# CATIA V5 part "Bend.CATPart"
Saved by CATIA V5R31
Part number: Bend
Bounding box of the stored display mesh (mm): x -50 to 50, y -150 to 15, z -50 to 115
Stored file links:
  D:\PROJECTS\Project 2021\US EDITION\CATIA V5 6R 2021\Resources\Part Files\c12_catia_v5_6r2021_prt\c12_catia_v5-6r2021 figr_12-39\Bend.CATPart
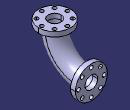
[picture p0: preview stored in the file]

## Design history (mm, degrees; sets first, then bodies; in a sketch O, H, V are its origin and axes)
Body1 (main body)
  Sketch1 on yz-plane, origin (0, 0, 0), H (0, 1, 0), V (0, 0, 1)
    arc A1 centre (0, 100) radius 100 from (-100, 100) to (0, 0) ccw
    point P1 (0, 100)
    coincidence: P1 V
  Sketch2 on zx-plane, origin (0, 0, 0), H (-1, 0, 0), V (0, 0, 1)
    circle A1 centre (0, 0) radius 30
    point P1 (0, -30)
    radius A1 = 30
    coincidence: A1 P1, P1 V
  Rib1: profile Sketch2, centre curve Sketch1
  Sketch3 on face of Rib1, origin (0, 0, 0), H (-1, 0, 0), V (0, 0, 1)
    circle A1 centre (0, 0) radius 50
    point P1 (0, -50)
    radius A1 = 50
    coincidence: A1 P1, P1 V
  Pad1: profile Sketch3, direction (0, 1, 0), length 15
  Sketch4 on face of Rib1, origin (0, 0, 100), H (1, 0, 0), V (0, 1, 0)
    circle A1 centre (0, -100) radius 50
    point P1 (0, -100)
    reference projected circle E1 centre (0, -100) radius 30 from edge [face of Rib1 | face of Rib1]
    radius A1 = 50
    coincidence: P1 V
    concentricity: A1 E1
  Pad2: profile Sketch4, direction (0, 0, 1), length 15
  Sketch5 on face of Pad1, origin (0, 15, 0), H (-1, 0, 0), V (0, 0, 1)
    circle A1 centre (0, 0) radius 20
    radius A1 = 20
  Sketch6 on yz-plane, origin (0, 0, 0), H (0, 1, 0), V (0, 0, 1)
    projected arc E1 centre (0, 100) radius 100 from (-100, 100) to (0, 0) ccw from edge of Sketch1
    line L1 (-100, 100) -> (-100, 115)
    point P3 (-100, 115)
    line L2 (0, 0) -> (15, 0)
    point P4 (15, 0)
    reference projected line E2 (15, 50) -> (15, -50) from edge [face of Pad1 | face of Pad1]
    reference projected line E3 (-50, 115) -> (-150, 115) from edge [face of Pad2 | face of Pad2]
    tangency: L1 E1, L2 E1
    coincidence: P4 E2, P3 E3
  Slot1: profile Sketch5, centre curve Sketch6
  Sketch7 on face of Pad1, origin (0, 15, 0), H (-1, 0, 0), V (0, 0, 1)
    circle A1 centre (0, -40) radius 6
    point P1 (0, -40)
    radius A1 = 6
    distance H P1 = 40
    coincidence: P1 V
  Pocket1: profile Sketch7, direction (0, -1, 0), length 15
  CircPattern1: of Pocket1, instances 8, angular step 45, axis from face of Pad1
  Sketch8 on face of Pad2, origin (0, 0, 115), H (1, 0, 0), V (0, 1, 0)
    circle A1 centre (0, -140) radius 6
    point P1 (0, -140)
    reference projected point E1 (0, -100) from vertex of Sketch1
    radius A1 = 6
    distance E1 P1 = 40
    coincidence: P1 V
  Pocket2: profile Sketch8, direction (0, 0, -1), length 15
  CircPattern2: of Pocket2, instances 8, angular step 45, axis from face of Pad2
